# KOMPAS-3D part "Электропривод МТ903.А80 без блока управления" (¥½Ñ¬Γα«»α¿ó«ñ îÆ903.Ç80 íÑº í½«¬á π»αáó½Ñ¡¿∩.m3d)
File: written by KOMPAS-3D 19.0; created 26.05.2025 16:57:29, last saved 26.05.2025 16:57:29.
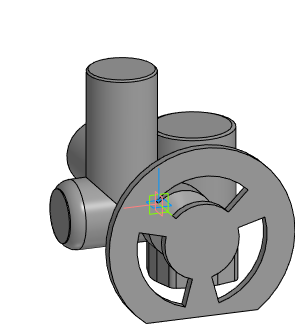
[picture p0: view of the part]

Document properties: Полное имя файла: E:\Dendor Работа Сачек\3D для проекитирвщиков\3.4 Электропривод МТ903.А\stp_Тип МТ903.А без блока управления\Электропривод МТ903.А80 без блока управления.m3d

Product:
- Part/product: Электропривод МТ903.А80 без блока управления

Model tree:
1. Операция без истории:1  (labels: Электропривод МТ903.А80 без блока управления)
